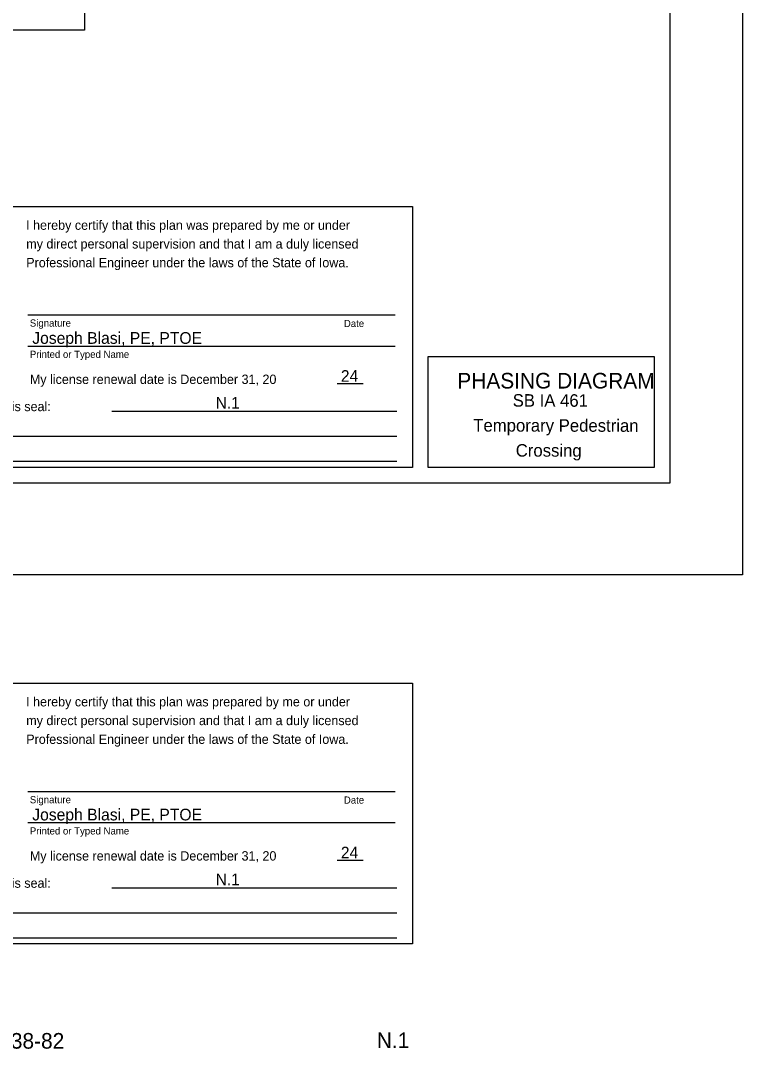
# Model space of a CAD drawing. Extents: x 10040 to 81668, y 7194 to 11018.
# Drawn here: x 12436 to 13360, y 7194 to 8516 of the extents above; entities that cross this region are included whole.
import ezdxf

# ---------------------------------------------------------------- set-up
doc = ezdxf.new("R2010")
doc.units = 0
for name, color, linetype in [('dsnCellElements', 7, 'Continuous'), ('dsnCellsSignature', 7, 'Continuous'), ('DsnShtAttachmentPoints', 7, 'Continuous'), ('dsnTextCpn', 7, 'Continuous'), ('Level 12', 7, 'Continuous'), ('Level 3', 7, 'Continuous'), ('Level 4', 7, 'Continuous'), ('wetSpecialNote', 7, 'Continuous')]:
    doc.layers.add(name, color=color, linetype=linetype)

msp = doc.modelspace()

# ---------------------------------------------------------------- linework, layer by layer
at = {"layer": 'dsnCellElements'}
msp.add_lwpolyline([(10039.6, 10000), (13360.5, 10000), (13360.5, 7806.6), (10039.6, 7806.6)], close=True, dxfattribs=at)
at = {"layer": 'dsnCellsSignature'}
for p, q in [((12915.7, 8139), (12445.7, 8139)), ((12915.7, 8099), (12445.7, 8099)), ((12875.1, 8051), (12841.5, 8051)), ((12553.1, 8016), (12918.1, 8016)), ((12208.2, 7984), (12918.1, 7984)), ((12208.2, 7952), (12918.1, 7952)), ((12915.7, 7528.8), (12445.7, 7528.8)), ((12915.7, 7488.8), (12445.7, 7488.8)), ((12875.1, 7440.8), (12841.5, 7440.8)), ((12553.1, 7405.8), (12918.1, 7405.8)), ((12208.2, 7373.8), (12918.1, 7373.8)), ((12208.2, 7341.8), (12918.1, 7341.8))]:
    msp.add_line(p, q, dxfattribs=at)
for points in [[(12188.1, 8278.1), (12938.1, 8278.1), (12938.1, 7944), (12188.1, 7944)], [(12188.1, 7667.9), (12938.1, 7667.9), (12938.1, 7333.8), (12188.1, 7333.8)]]:
    msp.add_lwpolyline(points, close=True, dxfattribs=at)
at = {"layer": 'Level 3'}
msp.add_lwpolyline([(10132.5, 9944), (13267.5, 9944), (13267.5, 7924), (10132.5, 7924)], close=True, dxfattribs=at)
msp.add_lwpolyline([(10132.5, 9944), (13267.5, 9944), (13267.5, 7924), (10132.5, 7924)], close=True, dxfattribs=at)
at = {"layer": 'Level 4'}
msp.add_lwpolyline([(10868.3, 8853.8), (12518.3, 8853.8), (12518.3, 8503.8), (10868.3, 8503.8)], close=True, dxfattribs=at)
at = {"layer": 'wetSpecialNote'}
msp.add_lwpolyline([(12958.1, 8085.8), (13247.5, 8085.8), (13247.5, 7944), (12958.1, 7944)], close=True, dxfattribs=at)

# ---------------------------------------------------------------- texts
at = {"layer": 'dsnCellsSignature'}
for s, height, p in [('I hereby certify that this plan was prepared by me or under', 12, (12443.3, 8248.2)), ('my direct personal supervision and that I am a duly licensed', 12, (12443.5, 8224.2)), ('Professional Engineer under the laws of the State of Iowa.', 12, (12443.5, 8200.2)), ('Signature', 9.2, (12448.1, 8124.2)), ('Date', 9.2, (12850.2, 8123.7)), ('Printed or Typed Name', 9.2, (12448.1, 8084.2)), ('My license renewal date is December 31, 20', 12, (12448.1, 8050.8)), ('Pages or sheets covered by this seal:', 12, (12208.2, 8016)), ('I hereby certify that this plan was prepared by me or under', 12, (12443.3, 7638)), ('my direct personal supervision and that I am a duly licensed', 12, (12443.5, 7614)), ('Professional Engineer under the laws of the State of Iowa.', 12, (12443.5, 7590)), ('Signature', 9.2, (12448.1, 7514)), ('Date', 9.2, (12850.2, 7513.5)), ('Printed or Typed Name', 9.2, (12448.1, 7474)), ('My license renewal date is December 31, 20', 12, (12448.1, 7440.6)), ('Pages or sheets covered by this seal:', 12, (12208.2, 7405.8))]:
    msp.add_text(s, height=height, dxfattribs=at).set_placement(p)
at = {"layer": 'DsnShtAttachmentPoints'}
msp.add_text('N.1', height=20, dxfattribs=at).set_placement((12892.4, 7200.5))
at = {"layer": 'dsnTextCpn'}
msp.add_text('BRF-461-1(9)--38-82', height=20, dxfattribs=at).set_placement((12242.5, 7199.8))
at = {"layer": 'Level 12'}
for s, height, p in [('Joseph Blasi, PE, PTOE', 15, (12451.2, 8102.2)), ('24', 14.89, (12846.4, 8053.6)), ('N.1', 14.89, (12686, 8019.3)), ('Joseph Blasi, PE, PTOE', 15, (12451.2, 7492)), ('24', 14.89, (12846.4, 7443.4)), ('N.1', 14.89, (12686, 7409.1))]:
    msp.add_text(s, height=height, dxfattribs=at).set_placement(p)
at = {"layer": 'wetSpecialNote'}
msp.add_text('PHASING DIAGRAM', height=20, dxfattribs=at).set_placement((12995.5, 8045))
for s, p in [('SB IA 461', (13066.4, 8021.8)), ('Temporary Pedestrian', (13015.9, 7989.9)), ('Crossing', (13070.3, 7957.8))]:
    msp.add_text(s, height=16, rotation=359.8981, dxfattribs=at).set_placement(p)

doc.saveas('drawing.dxf')
